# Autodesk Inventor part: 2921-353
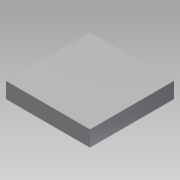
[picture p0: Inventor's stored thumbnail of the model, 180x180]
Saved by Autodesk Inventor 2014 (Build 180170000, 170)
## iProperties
Company: NHTSA/VRTC
Created: 2012-12
Part Number: 2921-353
Material: Steel, Mild
Document SubType Name: Modeling
Designer: Mike Vanvoorhis
Density: 7.86 g/cm^3
Mass: 193.203 g
Surface Area: 70.9676 cm^2
Volume: 24.5806 cm^3
Project: CHILD SIDE IMPACT SLED
Description: LOWER ANCHOR BASE TUBE END CAP
Stock Number: BAR 50.8 (2") x 9.5 (3/8") x 50.8 (2")
Appearance: Steel
Author: Dave Walker
Title: Lower Anchor Base Tube End Cap
Subject: Child Side Impact Sled
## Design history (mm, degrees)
sketch "Sketch1"
  geometry: L1 (0, 0)-(50.8, 0); L2 (50.8, 0)-(50.8, 9.525); L3 (50.8, 9.525)-(0, 9.525); L4 (0, 9.525)-(0, 0)
  constraints: 8 end point, 2 parallel, 1 horizontal, 1 perpendicular
  dimensions: "d0" = 50.8 distance of L3.end L2.end; "d1" = 9.525 distance of L2.end L1.end
extrude "Extrusion1" new body sketch "Sketch1" distance "d2" = 50.8; taper "d3" = 0 deg
body "Solid1"
